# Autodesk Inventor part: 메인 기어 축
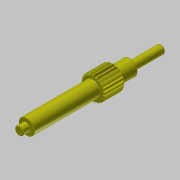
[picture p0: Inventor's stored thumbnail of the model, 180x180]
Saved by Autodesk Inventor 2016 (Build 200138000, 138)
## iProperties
Created: 2018-12
Part Number: 메인 기어 축
Material: 강철, 연강
Document SubType Name: Modeling
Designer: mduedu
Categories: <?xml version="1.0" encoding="UTF-16"?> <MemberInstance><Categories><FamilyTemplate><FamilyTemplateParameter ValueType="xs:double" Id="1" ObjectReferenceKey="da
Density: 7.86 g/cm^3
Appearance: 노란색
Mass: 179.676 g
Surface Area: 75.4119 cm^2
Volume: 22.8595 cm^3
CustomPartVersion: 1
Author: mduedu
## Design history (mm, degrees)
sketch "Sketch1"
  geometry: C1 r 11.3 at (0, 0)
  constraints: 1 centre point
  dimensions: "d0" = 22.6 diameter of C1 (= da_da)
extrude "Extrusion1" new body sketch "Sketch1" distance "d1" = 20 (= da_b); taper "d2" = 0 deg
workplane "Work Plane2"
sketch "Sketch2"
  geometry: C1 r 11.3 at (0, 0) reference; C2 r 10.5 at (0, 0)
  constraints: 1 centre point, 1 coincident
  dimensions: "d3" = 21 diameter of C2 (= da_dw)
feature "피치 지름" sketch "Sketch2" dims "d4" = 10, "d5" = 0
workplane "Work Plane8"
workplane "Work Plane9"
chamfer "모따기1" distance "d49" = 1; stored, may be unused: second distance "d50" = 2, angle "d51" = 45 deg
sketch "스케치3"
  geometry: C1 r 7.5 at (0, 0); 1 further point
  constraints: 1 centre point, 1 coincident
  dimensions: "d52" = 15 diameter of C1
extrude "돌출2" join sketch "스케치3" distance "d53" = 64; taper "d54" = 0 deg
sketch "스케치4"
  geometry: C1 r 4 at (0, 0); 1 further point
  constraints: 1 centre point, 1 coincident
  dimensions: "d55" = 8 diameter of C1
extrude "돌출3" join sketch "스케치4" distance "d56" = 7; taper "d57" = 0 deg
sketch "스케치5"
  geometry: C1 r 7.5 at (0, 0) reference; C2 r 7.5 at (0, 0) reference; 1 further point
extrude "돌출4" join sketch "스케치5" distance "d58" = 16; taper "d59" = 0 deg
sketch "스케치6"
  geometry: C1 r 4 at (0, 0); 1 further point
  constraints: 1 centre point, 1 coincident
  dimensions: "d60" = 8 diameter of C1
extrude "돌출5" join sketch "스케치6" distance "d61" = 30; taper "d62" = 0 deg
chamfer "모따기2" distance "d63" = 0.5; stored, may be unused: second distance "d64" = 2, angle "d65" = 45 deg
fillet "모깎기1" dims "d66" = 0.5
feature "스퍼 기어" dims "d39" = 0, "da_b" = 20, "da_d" = 21, "da_aw" = 31, "da_da" = 22.6, "da_df" = 19.086, "da_dw" = 21, angle "da_beta" = 0 deg, "da_lefttooth" = 0, "da_righttooth" = 0
sketch "스케치7" dims "d67" = 18
  geometry: C1 r 0.25 at (0, -9); 2 further points
  constraints: 2 vertical alignment, 1 centre point, 1 coincident, 2 other
  dimensions: "d68" = 0.5 diameter of C1
extrude "돌출6" join sketch "스케치7" distance "d69" = 0.3; taper "d70" = 0 deg
body "Solid1"
body "Srf1"
node "투영된 루프1"
other parameters: "d16" = 31 (= da_aw), "d17" = 0, "d34" = 1.496 (computed from da_z), "d41" = 0, "d43" = 31 (= da_aw), "d46" = 31 (= da_aw), "d47" = 0, "d48" = 0
